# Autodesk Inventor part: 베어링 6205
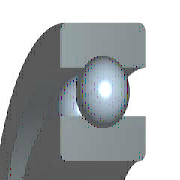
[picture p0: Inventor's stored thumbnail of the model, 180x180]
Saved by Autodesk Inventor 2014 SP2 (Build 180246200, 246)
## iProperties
IsCustomPart: 1
Company: 한국ATC센터
Created: 2014-10
Part Number: 베어링 6205
Material: 강, 연강
Description: 깊은 그루브 볼 베어링
Document SubType Name: Modeling
Standard: KS B 2023
Designer: 한국ATC센터
Standards Organization: KS
Language: ko-KR
Size Designation: 6205 - 25 x 52 x 15
Categories: <MemberInstance><Categories><Category DisplayName="샤프트 부품" InternalName="7f7aeb1f-a693-4053-b835-cee3144e0d98" Mnemonic="SHFT"><Category DisplayName="베어링" Inter
Density: 7.86 g/cm^3
Mass: 129.543 g
Surface Area: 107.326 cm^2
Volume: 16.4813 cm^3
Appearance: 강철
Author: KYOUNG IL JANG
Revision Number: 1
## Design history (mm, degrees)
sketch "스케치" dims "d0" = 7.02 (= -0.26 x WD + 0.26 x BD)
  geometry: L1 (3.99, 19.25)-(11.01, 19.25); L2 (7.5, 19.25)-(7.5, 15.74); L3 (7.5, 19.25)-(7.5, 22.76); L4 (4.892, 16.901)-(0, 16.901); L5 (0, 12.5)-(15, 12.5); L6 (4.892, 21.599)-(0, 21.599); L7 (0, 26)-(15, 26); L8 (15, 12.5)-(15, 16.901); L9 (10.108, 16.901)-(15, 16.901); L10 (10.108, 21.599)-(15, 21.599); L11 (15, 26)-(15, 21.599); L12 (-1.4, 0)-(8.4, 0) reference; L13 (0, -0.3)-(0, 5.3) reference
  constraints: 22 end point, 4 point on line, 2 collinear, 2 perpendicular, 2 symmetric about line, 1 midpoint, 1 parallel, 14 other
  dimensions: "d9" = 25 diameter of L5 L12 (= WD); "d11" = 52 diameter of L7 L12 (= BD); "d12" = 15 distance between parallel lines of L8 L13 (= KB); "d13" = 33.802 diameter of L9 L12 (= 0.326 x BD + 0.674 x WD)
revolve "본체" stored, may be unused: angle "d6" = 90 deg
revolve "볼" stored, may be unused: angle "d7" = 90 deg
pattern_circular "IDS_ARRAYBALL[SIMPL:T]" dims angle "d3" = 360 deg
body "Solid1"
fillet "모깎기1" dims "d1" = 1 (= KRS)
other parameters: "WD" = 25 [user parameter; used in 5 equation terms], "BD" = 52 [user parameter; used in 5 equation terms], "KB" = 15 [user parameter; used in 1 equation term], "KRS" = 1 [user parameter; used in 1 equation term], "d4" = 0, "d5" = 0, "d8" = 0, "d14" = 0, "d15" = 0, "BBA" = 0 [user parameter], "BC0" = 7800000 [user parameter], "BC" = 1.4e+07 [user parameter], "BR" = 26 (= 0.5 x BD) [user parameter], "WR" = 12.5 (= 0.5 x WD) [user parameter]
